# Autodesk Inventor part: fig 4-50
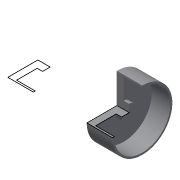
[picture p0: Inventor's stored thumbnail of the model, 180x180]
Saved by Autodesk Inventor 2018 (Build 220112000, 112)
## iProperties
Created: 2004-05
Part Number: fig 4-50
Document SubType Name: Modeling
Designer: CADCIM Technologies
Manufacturer: Standard
Standards Organization: Custom
Density: 1 g/cm^3
Material: Generic
Appearance: Default
Author: CADCIM Technologies
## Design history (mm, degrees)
sketch "Sketch1"
  geometry: L1 (30.083, 49.92)-(16.646, 49.92); L2 (16.646, 49.92)-(16.646, 17.104); L3 (16.646, 17.104)-(44.553, 17.104); L4 (44.553, 17.104)-(44.553, 19.171); L5 (44.553, 19.171)-(24.139, 19.171); L6 (24.139, 19.171)-(24.139, 41.652); L7 (24.139, 41.652)-(30.083, 41.652); L8 (30.083, 41.652)-(30.083, 49.92); L9 (116.437, 49.92)-(103, 49.92); L10 (103, 49.92)-(103, 17.104); L11 (103, 17.104)-(130.907, 17.104); L12 (130.907, 17.104)-(130.907, 19.171); L13 (130.907, 19.171)-(110.494, 19.171); L14 (110.494, 19.171)-(110.494, 41.652); L15 (110.494, 41.652)-(116.437, 41.652); L16 (116.437, 41.652)-(116.437, 49.92)
  constraints: 32 end point, 2 horizontal
revolve "Revolution1" sketch "Sketch1" stored, may be unused: angle "d0" = 270 deg
body "Solid1"
